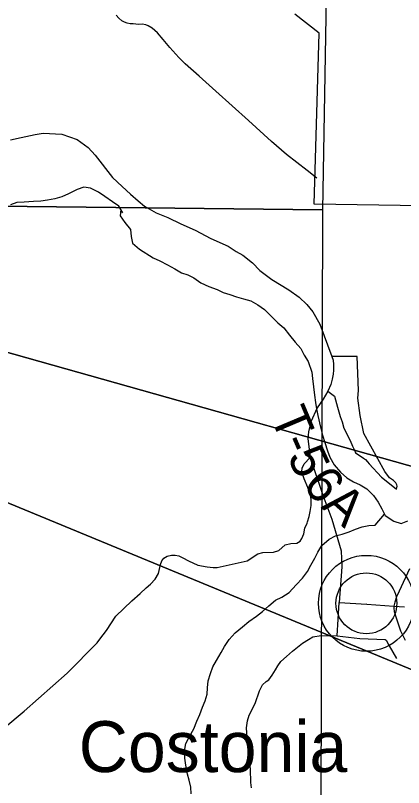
# Model space of a CAD drawing. Extents: x 0 to 34, y 0 to 22.
# Drawn here: x 6.964 to 7.567, y 16.204 to 17.402 of the extents above; entities that cross this region are included whole.
import ezdxf

# ---------------------------------------------------------------- set-up
doc = ezdxf.new("R2010")
doc.units = 0
for name, color, linetype in [('GM_X_Corporation', 7, 'Continuous'), ('GM_X_County_Road', 7, 'Continuous'), ('GM_X_Interchange_Ramps', 7, 'Continuous'), ('GM_X_Minor_River', 7, 'Continuous'), ('GM_X_Section', 7, 'Continuous'), ('GM_X_Township_Road', 7, 'Continuous'), ('GM_X_Township_Road_Text', 7, 'Continuous'), ('GM_X_Unincorporated', 7, 'Continuous'), ('GM_X_Unincorporated_Location', 7, 'Continuous'), ('GM_X_Unincorporated_Text', 7, 'Continuous'), ('SC_Shading1', 7, 'Continuous'), ('SH_Data', 7, 'Continuous')]:
    doc.layers.add(name, color=color, linetype=linetype)

msp = doc.modelspace()

# ---------------------------------------------------------------- linework, layer by layer
at = {"layer": 'GM_X_Corporation'}
for p, q in [((7.4355, 17.3741), (7.3981, 17.4037)), ((7.4277, 17.1087), (7.4355, 17.3741)), ((7.6075, 17.1058), (7.4277, 17.1087))]:
    msp.add_line(p, q, dxfattribs=at)
at = {"layer": 'GM_X_County_Road'}
for p, q in [((6.9733, 17.2121), (6.9949, 17.2169)), ((6.9949, 17.2169), (7.0071, 17.2188)), ((7.0071, 17.2188), (7.0364, 17.2172)), ((7.0364, 17.2172), (7.0602, 17.2092)), ((6.9567, 17.2088), (6.9733, 17.2121)), ((7.0602, 17.2092), (7.0772, 17.1966)), ((7.0772, 17.1966), (7.0882, 17.1851)), ((7.0882, 17.1851), (7.1148, 17.15)), ((7.1148, 17.15), (7.1297, 17.1362)), ((7.1297, 17.1362), (7.1428, 17.1241)), ((7.1428, 17.1241), (7.1547, 17.1138)), ((7.1547, 17.1138), (7.1644, 17.1055)), ((7.1644, 17.1055), (7.1827, 17.0952)), ((7.1827, 17.0952), (7.201, 17.0881)), ((7.201, 17.0881), (7.2211, 17.0784)), ((7.2211, 17.0784), (7.2434, 17.0683)), ((7.2434, 17.0683), (7.2676, 17.0553)), ((7.2676, 17.0553), (7.2945, 17.0438)), ((7.2945, 17.0438), (7.3069, 17.0355)), ((7.3069, 17.0355), (7.3172, 17.0296)), ((7.3172, 17.0296), (7.3322, 17.0176)), ((7.3322, 17.0176), (7.3437, 17.0057)), ((7.3437, 17.0057), (7.3623, 16.9917)), ((7.3623, 16.9917), (7.3885, 16.9759)), ((7.3885, 16.9759), (7.4048, 16.9647)), ((7.4048, 16.9647), (7.4167, 16.9532)), ((7.4167, 16.9532), (7.4259, 16.9417)), ((7.4259, 16.9417), (7.4366, 16.9227)), ((7.4366, 16.9227), (7.4553, 16.8724)), ((7.4553, 16.8724), (7.4572, 16.8666)), ((7.4572, 16.8666), (7.4577, 16.8598)), ((7.4577, 16.8598), (7.4578, 16.8577)), ((7.4578, 16.8577), (7.4578, 16.8515)), ((7.4578, 16.8515), (7.4573, 16.8449)), ((7.4561, 16.8373), (7.4536, 16.8288)), ((7.4573, 16.8449), (7.4561, 16.8373)), ((7.4536, 16.8288), (7.4489, 16.8188)), ((7.4489, 16.8188), (7.4419, 16.8062)), ((7.4419, 16.8062), (7.4324, 16.793)), ((7.4324, 16.793), (7.4226, 16.771)), ((7.4226, 16.771), (7.4193, 16.7554)), ((7.4193, 16.7554), (7.418, 16.7451)), ((7.418, 16.7451), (7.4218, 16.7158)), ((7.4218, 16.7158), (7.4416, 16.6571)), ((7.4416, 16.6571), (7.4554, 16.6201)), ((7.4554, 16.6201), (7.4697, 16.5709)), ((7.4697, 16.5709), (7.4711, 16.546)), ((7.4711, 16.546), (7.467, 16.491)), ((7.467, 16.491), (7.5098, 16.4879)), ((7.5098, 16.4879), (7.5514, 16.4853)), ((7.5514, 16.4853), (7.568, 16.484))]:
    msp.add_line(p, q, dxfattribs=at)
at = {"layer": 'GM_X_Interchange_Ramps'}
for p, q in [((7.5757, 16.5428), (7.56, 16.5083)), ((7.5558, 16.4995), (7.5532, 16.4912)), ((7.56, 16.5083), (7.5558, 16.4995)), ((7.5532, 16.4912), (7.5514, 16.4853)), ((7.5514, 16.4853), (7.5514, 16.4817)), ((7.5514, 16.4817), (7.5521, 16.4767)), ((7.5521, 16.4767), (7.5556, 16.4653)), ((7.5556, 16.4653), (7.5622, 16.4466)), ((7.5622, 16.4466), (7.5694, 16.4321))]:
    msp.add_line(p, q, dxfattribs=at)
at = {"layer": 'GM_X_Minor_River'}
for p, q in [((7.0704, 17.1352), (7.0598, 17.1318)), ((7.0807, 17.1336), (7.0704, 17.1352)), ((7.093, 17.1275), (7.0807, 17.1336)), ((7.0464, 17.1249), (7.0362, 17.1204)), ((7.0598, 17.1318), (7.0464, 17.1249)), ((7.1031, 17.1206), (7.093, 17.1275)), ((6.9665, 17.1114), (6.9568, 17.108)), ((6.9779, 17.1117), (6.9665, 17.1114)), ((6.9924, 17.113), (6.9779, 17.1117)), ((7.0034, 17.1137), (6.9924, 17.113)), ((7.014, 17.1148), (7.0034, 17.1137)), ((7.0253, 17.117), (7.014, 17.1148)), ((7.0362, 17.1204), (7.0253, 17.117)), ((7.1148, 17.1122), (7.1031, 17.1206)), ((7.1249, 17.1057), (7.1148, 17.1122)), ((7.131, 17.0952), (7.1249, 17.1057)), ((7.1279, 17.1006), (7.1268, 17.0907)), ((7.1268, 17.0907), (7.1342, 17.0802)), ((7.1342, 17.0802), (7.1429, 17.0694)), ((7.1429, 17.0694), (7.1439, 17.0587)), ((7.1439, 17.0587), (7.1461, 17.0481)), ((7.1461, 17.0481), (7.157, 17.0389)), ((7.157, 17.0389), (7.1779, 17.0257)), ((7.1779, 17.0257), (7.1886, 17.0207)), ((7.1886, 17.0207), (7.2002, 17.0149)), ((7.2002, 17.0149), (7.2118, 17.0083)), ((7.2118, 17.0083), (7.2222, 17.0022)), ((7.2222, 17.0022), (7.2318, 16.999)), ((7.2318, 16.999), (7.2414, 16.9943)), ((7.2414, 16.9943), (7.2522, 16.987)), ((7.2522, 16.987), (7.2642, 16.9812)), ((7.2642, 16.9812), (7.2772, 16.9762)), ((7.2772, 16.9762), (7.2868, 16.9719)), ((7.2868, 16.9719), (7.2972, 16.9687)), ((7.2972, 16.9687), (7.3072, 16.9652)), ((7.3072, 16.9652), (7.3183, 16.9621)), ((7.3183, 16.9621), (7.3298, 16.9586)), ((7.3298, 16.9586), (7.3405, 16.9528)), ((7.3405, 16.9528), (7.3506, 16.9454)), ((7.3506, 16.9454), (7.3615, 16.9347)), ((7.3615, 16.9347), (7.3713, 16.9246)), ((7.3713, 16.9246), (7.381, 16.9169)), ((7.381, 16.9169), (7.3897, 16.9057)), ((7.3897, 16.9057), (7.3987, 16.8949)), ((7.3987, 16.8949), (7.4073, 16.8848)), ((7.4073, 16.8848), (7.4125, 16.8743)), ((7.4125, 16.8743), (7.4185, 16.8646)), ((7.4185, 16.8646), (7.4243, 16.848)), ((7.4243, 16.848), (7.4253, 16.8385)), ((7.4253, 16.8385), (7.4268, 16.8252)), ((7.4268, 16.8252), (7.4286, 16.8123)), ((7.4286, 16.8123), (7.4301, 16.8009)), ((7.4301, 16.8009), (7.4315, 16.791)), ((7.4315, 16.791), (7.4336, 16.7811)), ((7.4336, 16.7811), (7.4379, 16.763)), ((7.4379, 16.763), (7.4409, 16.7505)), ((7.4409, 16.7505), (7.4446, 16.7388)), ((7.4446, 16.7388), (7.4484, 16.7263)), ((7.4484, 16.7263), (7.4525, 16.7161)), ((7.4525, 16.7161), (7.4592, 16.7045)), ((7.4592, 16.7045), (7.4687, 16.6929)), ((7.4687, 16.6929), (7.4784, 16.6841)), ((7.4784, 16.6841), (7.4888, 16.6779)), ((7.4888, 16.6779), (7.4992, 16.6732)), ((7.4992, 16.6732), (7.5096, 16.667)), ((7.5096, 16.667), (7.5198, 16.657)), ((7.5198, 16.657), (7.5273, 16.6465)), ((7.5273, 16.6465), (7.5329, 16.636)), ((7.5329, 16.636), (7.5381, 16.6259)), ((7.5225, 16.6106), (7.5372, 16.6277)), ((7.5372, 16.6277), (7.5377, 16.6278)), ((7.5381, 16.6259), (7.5516, 16.6167)), ((7.4923, 16.6045), (7.5025, 16.6082)), ((7.5025, 16.6082), (7.5127, 16.6103)), ((7.5127, 16.6103), (7.5225, 16.6106)), ((7.5516, 16.6167), (7.5628, 16.6132)), ((7.5628, 16.6132), (7.5733, 16.6173)), ((7.4513, 16.5889), (7.461, 16.5941)), ((7.461, 16.5941), (7.4712, 16.597)), ((7.4712, 16.597), (7.4821, 16.6004)), ((7.4821, 16.6004), (7.4923, 16.6045)), ((7.4398, 16.5794), (7.4513, 16.5889)), ((7.4336, 16.569), (7.4398, 16.5794)), ((7.4227, 16.5489), (7.4289, 16.5593)), ((7.4289, 16.5593), (7.4336, 16.569)), ((7.4177, 16.5388), (7.4227, 16.5489)), ((7.41, 16.5283), (7.4177, 16.5388)), ((7.4, 16.5182), (7.41, 16.5283)), ((7.3893, 16.5064), (7.4, 16.5182)), ((7.3679, 16.4944), (7.3777, 16.4989)), ((7.3777, 16.4989), (7.3893, 16.5064)), ((7.3479, 16.4768), (7.3575, 16.4858)), ((7.3575, 16.4858), (7.3679, 16.4944)), ((7.3382, 16.4696), (7.3479, 16.4768)), ((7.3266, 16.4613), (7.3382, 16.4696)), ((7.3054, 16.4436), (7.3166, 16.4531)), ((7.3166, 16.4531), (7.3266, 16.4613)), ((7.2962, 16.4331), (7.3054, 16.4436)), ((7.2889, 16.4226), (7.2962, 16.4331)), ((7.2835, 16.4129), (7.2889, 16.4226)), ((7.2762, 16.4009), (7.2835, 16.4129)), ((7.2672, 16.3805), (7.2704, 16.3909)), ((7.2704, 16.3909), (7.2762, 16.4009)), ((7.2634, 16.369), (7.2672, 16.3805)), ((7.2625, 16.3583), (7.2634, 16.369)), ((7.2616, 16.3484), (7.2625, 16.3583)), ((7.2585, 16.3384), (7.2616, 16.3484)), ((7.2546, 16.3284), (7.2585, 16.3384)), ((7.2503, 16.3169), (7.2546, 16.3284)), ((7.241, 16.2949), (7.246, 16.3068)), ((7.246, 16.3068), (7.2503, 16.3169)), ((7.2345, 16.2829), (7.241, 16.2949)), ((7.2287, 16.2721), (7.2345, 16.2829)), ((7.2268, 16.2599), (7.2287, 16.2721)), ((7.2271, 16.2492), (7.2268, 16.2599)), ((7.2289, 16.2382), (7.2271, 16.2492)), ((7.2311, 16.2246), (7.2289, 16.2382)), ((7.2337, 16.2148), (7.2311, 16.2246)), ((7.2363, 16.2042), (7.2337, 16.2148)), ((7.2369, 16.1939), (7.2363, 16.2042))]:
    msp.add_line(p, q, dxfattribs=at)
at = {"layer": 'GM_X_Section'}
for p, q in [((7.457, 18.0478), (7.441, 17.0998)), ((7.441, 17.0998), (6.4366, 17.1114)), ((6.4366, 17.1114), (7.441, 17.0998)), ((7.441, 17.0998), (7.438, 16.0393))]:
    msp.add_line(p, q, dxfattribs=at)
at = {"layer": 'GM_X_Township_Road'}
for p, q in [((7.1245, 17.3977), (7.1205, 17.402)), ((7.1292, 17.3932), (7.1245, 17.3977)), ((7.1333, 17.3912), (7.1292, 17.3932)), ((7.1376, 17.3897), (7.1333, 17.3912)), ((7.1421, 17.3887), (7.1376, 17.3897)), ((7.147, 17.3889), (7.1421, 17.3887)), ((7.1553, 17.3875), (7.147, 17.3889)), ((7.1608, 17.388), (7.1553, 17.3875)), ((7.1666, 17.3871), (7.1608, 17.388)), ((7.1704, 17.3854), (7.1666, 17.3871)), ((7.1767, 17.3818), (7.1704, 17.3854)), ((7.1845, 17.3747), (7.1767, 17.3818)), ((7.1934, 17.3645), (7.1845, 17.3747)), ((7.2039, 17.3518), (7.1934, 17.3645)), ((7.2181, 17.3364), (7.2039, 17.3518)), ((7.2275, 17.3264), (7.2181, 17.3364)), ((7.2495, 17.3073), (7.2275, 17.3264)), ((7.2752, 17.2844), (7.2495, 17.3073)), ((7.3258, 17.2384), (7.2752, 17.2844)), ((7.3619, 17.2059), (7.3258, 17.2384)), ((7.385, 17.1858), (7.3619, 17.2059)), ((7.417, 17.1609), (7.385, 17.1858)), ((7.4322, 17.149), (7.417, 17.1609)), ((7.4947, 16.8725), (7.4553, 16.8724)), ((7.4969, 16.8198), (7.4947, 16.8725)), ((7.4489, 16.8188), (7.4593, 16.8107)), ((7.4593, 16.8107), (7.4644, 16.7939)), ((7.4959, 16.8079), (7.4969, 16.8198)), ((7.4995, 16.7809), (7.4959, 16.8079)), ((7.4644, 16.7939), (7.4682, 16.7793)), ((7.4682, 16.7793), (7.4715, 16.771)), ((7.5048, 16.7529), (7.4995, 16.7809)), ((7.4715, 16.771), (7.4738, 16.7613)), ((7.4738, 16.7613), (7.4836, 16.742)), ((7.5374, 16.6939), (7.5048, 16.7529)), ((7.4836, 16.742), (7.4876, 16.7331)), ((7.4876, 16.7331), (7.4903, 16.7273)), ((7.4903, 16.7273), (7.4923, 16.7228)), ((7.4124, 16.7061), (7.4218, 16.7158)), ((7.4923, 16.7228), (7.4962, 16.7202)), ((7.4962, 16.7202), (7.5045, 16.7149)), ((7.5045, 16.7149), (7.5076, 16.7125)), ((7.4095, 16.6994), (7.4124, 16.7061)), ((7.5076, 16.7125), (7.5107, 16.7092)), ((7.5107, 16.7092), (7.5132, 16.7061)), ((7.5132, 16.7061), (7.5324, 16.685)), ((7.4089, 16.694), (7.4095, 16.6994)), ((7.4122, 16.6825), (7.4089, 16.694)), ((7.5449, 16.6844), (7.5374, 16.6939)), ((7.4179, 16.669), (7.4122, 16.6825)), ((7.5324, 16.685), (7.5421, 16.6775)), ((7.5421, 16.6775), (7.5558, 16.6667)), ((7.551, 16.6799), (7.5449, 16.6844)), ((7.5547, 16.6762), (7.551, 16.6799)), ((7.422, 16.6573), (7.4179, 16.669)), ((7.5564, 16.6732), (7.5547, 16.6762)), ((7.5558, 16.6667), (7.5569, 16.671)), ((7.5569, 16.671), (7.5564, 16.6732)), ((7.4235, 16.6506), (7.422, 16.6573)), ((7.4218, 16.6322), (7.4233, 16.6414)), ((7.4233, 16.6414), (7.4235, 16.6506)), ((7.42, 16.6243), (7.4218, 16.6322)), ((7.4177, 16.6159), (7.42, 16.6243)), ((7.4118, 16.5974), (7.4137, 16.6063)), ((7.4137, 16.6063), (7.4169, 16.614)), ((7.4169, 16.614), (7.4177, 16.6159)), ((7.4087, 16.59), (7.4118, 16.5974)), ((7.383, 16.58), (7.3915, 16.5824)), ((7.3915, 16.5824), (7.4012, 16.583)), ((7.4012, 16.583), (7.4062, 16.5861)), ((7.4062, 16.5861), (7.4087, 16.59)), ((7.3648, 16.569), (7.3732, 16.5713)), ((7.3732, 16.5713), (7.383, 16.58)), ((7.1915, 16.5552), (7.1947, 16.5595)), ((7.1947, 16.5595), (7.1998, 16.5625)), ((7.1998, 16.5625), (7.2066, 16.5641)), ((7.2066, 16.5641), (7.2123, 16.5641)), ((7.2123, 16.5641), (7.2181, 16.5629)), ((7.2181, 16.5629), (7.2243, 16.56)), ((7.2243, 16.56), (7.233, 16.5553)), ((7.3241, 16.5556), (7.3406, 16.566)), ((7.3406, 16.566), (7.3481, 16.5685)), ((7.3481, 16.5685), (7.3648, 16.569)), ((7.1861, 16.5358), (7.1894, 16.5495)), ((7.1894, 16.5495), (7.1915, 16.5552)), ((7.233, 16.5553), (7.2476, 16.5485)), ((7.2476, 16.5485), (7.2617, 16.546)), ((7.2617, 16.546), (7.271, 16.5452)), ((7.2775, 16.5452), (7.3241, 16.5556)), ((7.181, 16.5268), (7.1861, 16.5358)), ((7.271, 16.5452), (7.2775, 16.5452)), ((7.174, 16.5193), (7.181, 16.5268)), ((7.1577, 16.5047), (7.1673, 16.5137)), ((7.1673, 16.5137), (7.174, 16.5193)), ((7.1448, 16.4932), (7.1577, 16.5047)), ((7.1199, 16.4693), (7.1448, 16.4932)), ((7.4635, 16.439), (7.467, 16.491)), ((7.1058, 16.4475), (7.1199, 16.4693)), ((7.0953, 16.4338), (7.1058, 16.4475)), ((7.4259, 16.4374), (7.4387, 16.4397)), ((7.4387, 16.4397), (7.4635, 16.439)), ((7.4635, 16.439), (7.4987, 16.4351)), ((7.0446, 16.381), (7.0909, 16.4282)), ((7.0909, 16.4282), (7.0953, 16.4338)), ((7.3942, 16.4152), (7.4097, 16.4274)), ((7.4097, 16.4274), (7.4192, 16.4334)), ((7.4192, 16.4334), (7.4259, 16.4374)), ((7.4987, 16.4351), (7.5381, 16.4333)), ((7.5381, 16.4333), (7.5399, 16.4324)), ((7.5399, 16.4324), (7.5445, 16.4235)), ((7.3852, 16.4071), (7.3942, 16.4152)), ((7.5445, 16.4235), (7.5557, 16.4041)), ((7.3762, 16.399), (7.3852, 16.4071)), ((7.3679, 16.3862), (7.3717, 16.3927)), ((7.3717, 16.3927), (7.3762, 16.399)), ((6.9777, 16.322), (7.0446, 16.381)), ((7.3578, 16.3705), (7.363, 16.3779)), ((7.363, 16.3779), (7.3679, 16.3862)), ((7.3477, 16.3631), (7.3532, 16.3679)), ((7.3532, 16.3679), (7.3578, 16.3705)), ((7.3432, 16.3537), (7.3477, 16.3631)), ((7.3362, 16.3338), (7.3432, 16.3537)), ((7.3273, 16.3159), (7.3362, 16.3338)), ((6.946, 16.2957), (6.9777, 16.322)), ((7.3231, 16.2963), (7.3246, 16.3071)), ((7.3246, 16.3071), (7.3273, 16.3159)), ((7.3251, 16.267), (7.3231, 16.2963)), ((7.3289, 16.2323), (7.3251, 16.267)), ((7.3295, 16.2115), (7.3289, 16.2323)), ((7.3309, 16.203), (7.3295, 16.2115))]:
    msp.add_line(p, q, dxfattribs=at)
at = {"layer": 'GM_X_Unincorporated'}
for radius in [0.0744, 0.0472]:
    msp.add_circle((7.509, 16.4895), radius, dxfattribs=at)
at = {"layer": 'GM_X_Unincorporated_Location'}
msp.add_line((7.509, 16.4895), (7.509, 16.4895), dxfattribs=at)
at = {"layer": 'SC_Shading1'}
msp.add_lwpolyline([(10.3861, 15.9111), (10.3861, 15.2276), (5.1721, 17.3806)], close=True, dxfattribs=at)
at = {"layer": 'SH_Data'}
msp.add_lwpolyline([(10.3861, 15.9111), (5.1721, 17.3806), (10.3861, 15.2276)], dxfattribs=at)

# ---------------------------------------------------------------- texts
at = {"layer": 'GM_X_Township_Road_Text'}
for s, rotation, p in [('T', 292.8424, (7.359, 16.7802)), ('-', 293.2861, (7.3757, 16.7406)), ('5', 294.8358, (7.3856, 16.7177)), ('6', 309.0889, (7.4085, 16.6728)), ('A', 318.4443, (7.4376, 16.6384))]:
    msp.add_text(s, height=0.0568, rotation=rotation, dxfattribs=at).set_placement(p)
at = {"layer": 'GM_X_Unincorporated_Text'}
msp.add_text('Costonia', height=0.07898, rotation=0, dxfattribs=at).set_placement((7.0625, 16.2276))

doc.saveas('drawing.dxf')
